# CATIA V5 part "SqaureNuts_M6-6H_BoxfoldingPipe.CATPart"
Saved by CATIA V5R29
Part number: SquareNuts_M6-6H_BoxFoldingPipe
Bounding box of the stored display mesh (mm): x -7 to 7, y -7 to 7, z -3 to 3
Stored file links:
  C:\Users\Administrator\Desktop\프로젝트\Boxfold\SqaureNuts_M6-6H_BoxfoldingPipe.CATPart
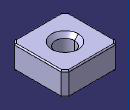
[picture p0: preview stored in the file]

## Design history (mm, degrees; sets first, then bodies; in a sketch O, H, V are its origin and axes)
Body1 (main body)
  Sketch1 on xy-plane, origin (0, 0, 0), H (1, 0, 0), V (0, 1, 0)
    line L1 (7, 7) -> (7, -7)
    line L2 (7, -7) -> (-7, -7)
    line L3 (-7, -7) -> (-7, 7)
    line L4 (-7, 7) -> (7, 7)
    length L3 = 14
    length L4 = 14
    vertical: L1 V, L3 V
    horizontal: L2 H, L4 H
    equidistance: L1 L3 O, L2 L4 O
  Pad1: profile Sketch1, direction (0, 0, 1), length 3, mirrored extent
  Sketch2 on end face of Pad1, origin (0.3753, 1.5089, 3), H (1, 0, 0), V (0, 1, 0)
    point P1 (-0.3753, -1.5089)
    reference projected line E1 (6.6247, -8.5089) -> (6.6247, 5.4911) from edge [face of Pad1 from Sketch1.L1 | end face of Pad1]
    reference projected line E2 (6.6247, 5.4911) -> (-7.3753, 5.4911) from edge [face of Pad1 from Sketch1.L4 | end face of Pad1]
    distance P1 E1 = 7
    distance E2 P1 = 7
  Hole1: placed by Sketch2, at (0, 0, 3) direction (0, 0, -1), diameter 4.917, through (limit type 3), threaded "M6", thread diameter 6, thread depth 6, pitch 1
  Chamfer1: length 1, angle 45, on face of Hole1; edge [face of Pad1 from Sketch1.L4 | face of Pad1 from Sketch1.L1]; edge [face of Pad1 from Sketch1.L3 | face of Pad1 from Sketch1.L4]; edge [face of Pad1 from Sketch1.L1 | face of Pad1 from Sketch1.L2]; edge [face of Pad1 from Sketch1.L2 | face of Pad1 from Sketch1.L3]
  Fillet1: radius 0.3, on edge [face of Pad1 from Sketch1.L3 | end face of Pad1]; edge [end face of Pad1 | face of Chamfer1] (x4); edge [face of Pad1 from Sketch1.L2 | end face of Pad1]; edge [face of Pad1 from Sketch1.L1 | end face of Pad1]; edge [face of Pad1 from Sketch1.L4 | end face of Pad1]; edge [start face of Pad1 | face of Pad1 from Sketch1.L3]; edge [start face of Pad1 | face of Chamfer1] (x4); edge [start face of Pad1 | face of Pad1 from Sketch1.L2]; edge [start face of Pad1 | face of Pad1 from Sketch1.L1]; edge [start face of Pad1 | face of Pad1 from Sketch1.L4]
